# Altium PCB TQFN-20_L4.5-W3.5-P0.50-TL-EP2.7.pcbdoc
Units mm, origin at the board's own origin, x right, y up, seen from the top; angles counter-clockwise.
Board outline 17.05 x 18.42 mm, 2 copper layers (Top Layer, Bottom Layer), stack 0 mm thick; 1 components, 0 nets, 21 pads, 0 vias.
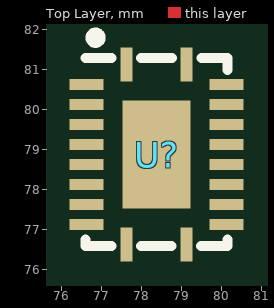
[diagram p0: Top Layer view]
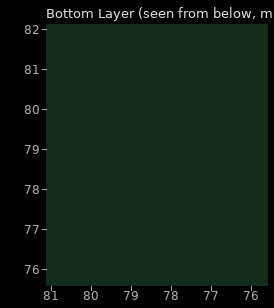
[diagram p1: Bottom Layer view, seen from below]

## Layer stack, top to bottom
Top Layer: signal copper (thickness not stored)
Bottom Layer: signal copper (thickness not stored)

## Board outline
86.9,69.85 69.85,69.85 69.85,88.273 86.9,88.273

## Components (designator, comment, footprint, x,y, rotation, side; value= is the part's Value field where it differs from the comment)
U? "" TQFN-20_L4.5-W3.5-P0.50-TL-EP2.7 78.375,78.875 r0 top

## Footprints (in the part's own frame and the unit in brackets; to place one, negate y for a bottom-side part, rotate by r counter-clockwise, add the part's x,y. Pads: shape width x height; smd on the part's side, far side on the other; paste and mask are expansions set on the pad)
TQFN-20_L4.5-W3.5-P0.50-TL-EP2.7 [mm]
  rect 0.3x0.85 smd paste+0 mask+0.05: 1(-0.75,2.25) 10(-0.75,-2.25) 11(0.75,-2.25) 20(0.75,2.25)
  rect 0.85x0.28 smd paste+0 mask+0.05: 2(-1.75,1.749) 3(-1.75,1.248) 4(-1.75,0.749) 5(-1.75,0.248) 6(-1.75,-0.251) 7(-1.75,-0.752) 8(-1.75,-1.251) 9(-1.75,-1.752) 12(1.75,-1.752) 13(1.75,-1.251) 14(1.748,-0.75) 15(1.748,-0.25) 16(1.748,0.25) 17(1.748,0.75) 18(1.748,1.25) 19(1.748,1.75)
  rect 1.7x2.7 smd paste+0 mask+0.05: 21(-0.002,0)
  silkscreen extent -1.78,-2.29 1.78,3.05

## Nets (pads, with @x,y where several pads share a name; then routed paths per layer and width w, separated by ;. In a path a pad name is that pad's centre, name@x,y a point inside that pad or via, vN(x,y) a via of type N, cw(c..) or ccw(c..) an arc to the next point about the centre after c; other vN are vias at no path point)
pads on no net: U?.1 U?.2 U?.3 U?.4 U?.5 U?.6 U?.7 U?.8 U?.9 U?.10 U?.11 U?.12 U?.13 U?.14 U?.15 U?.16 U?.17 U?.18 U?.19 U?.20 U?.21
